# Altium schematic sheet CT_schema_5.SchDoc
size 368 x 243 mm
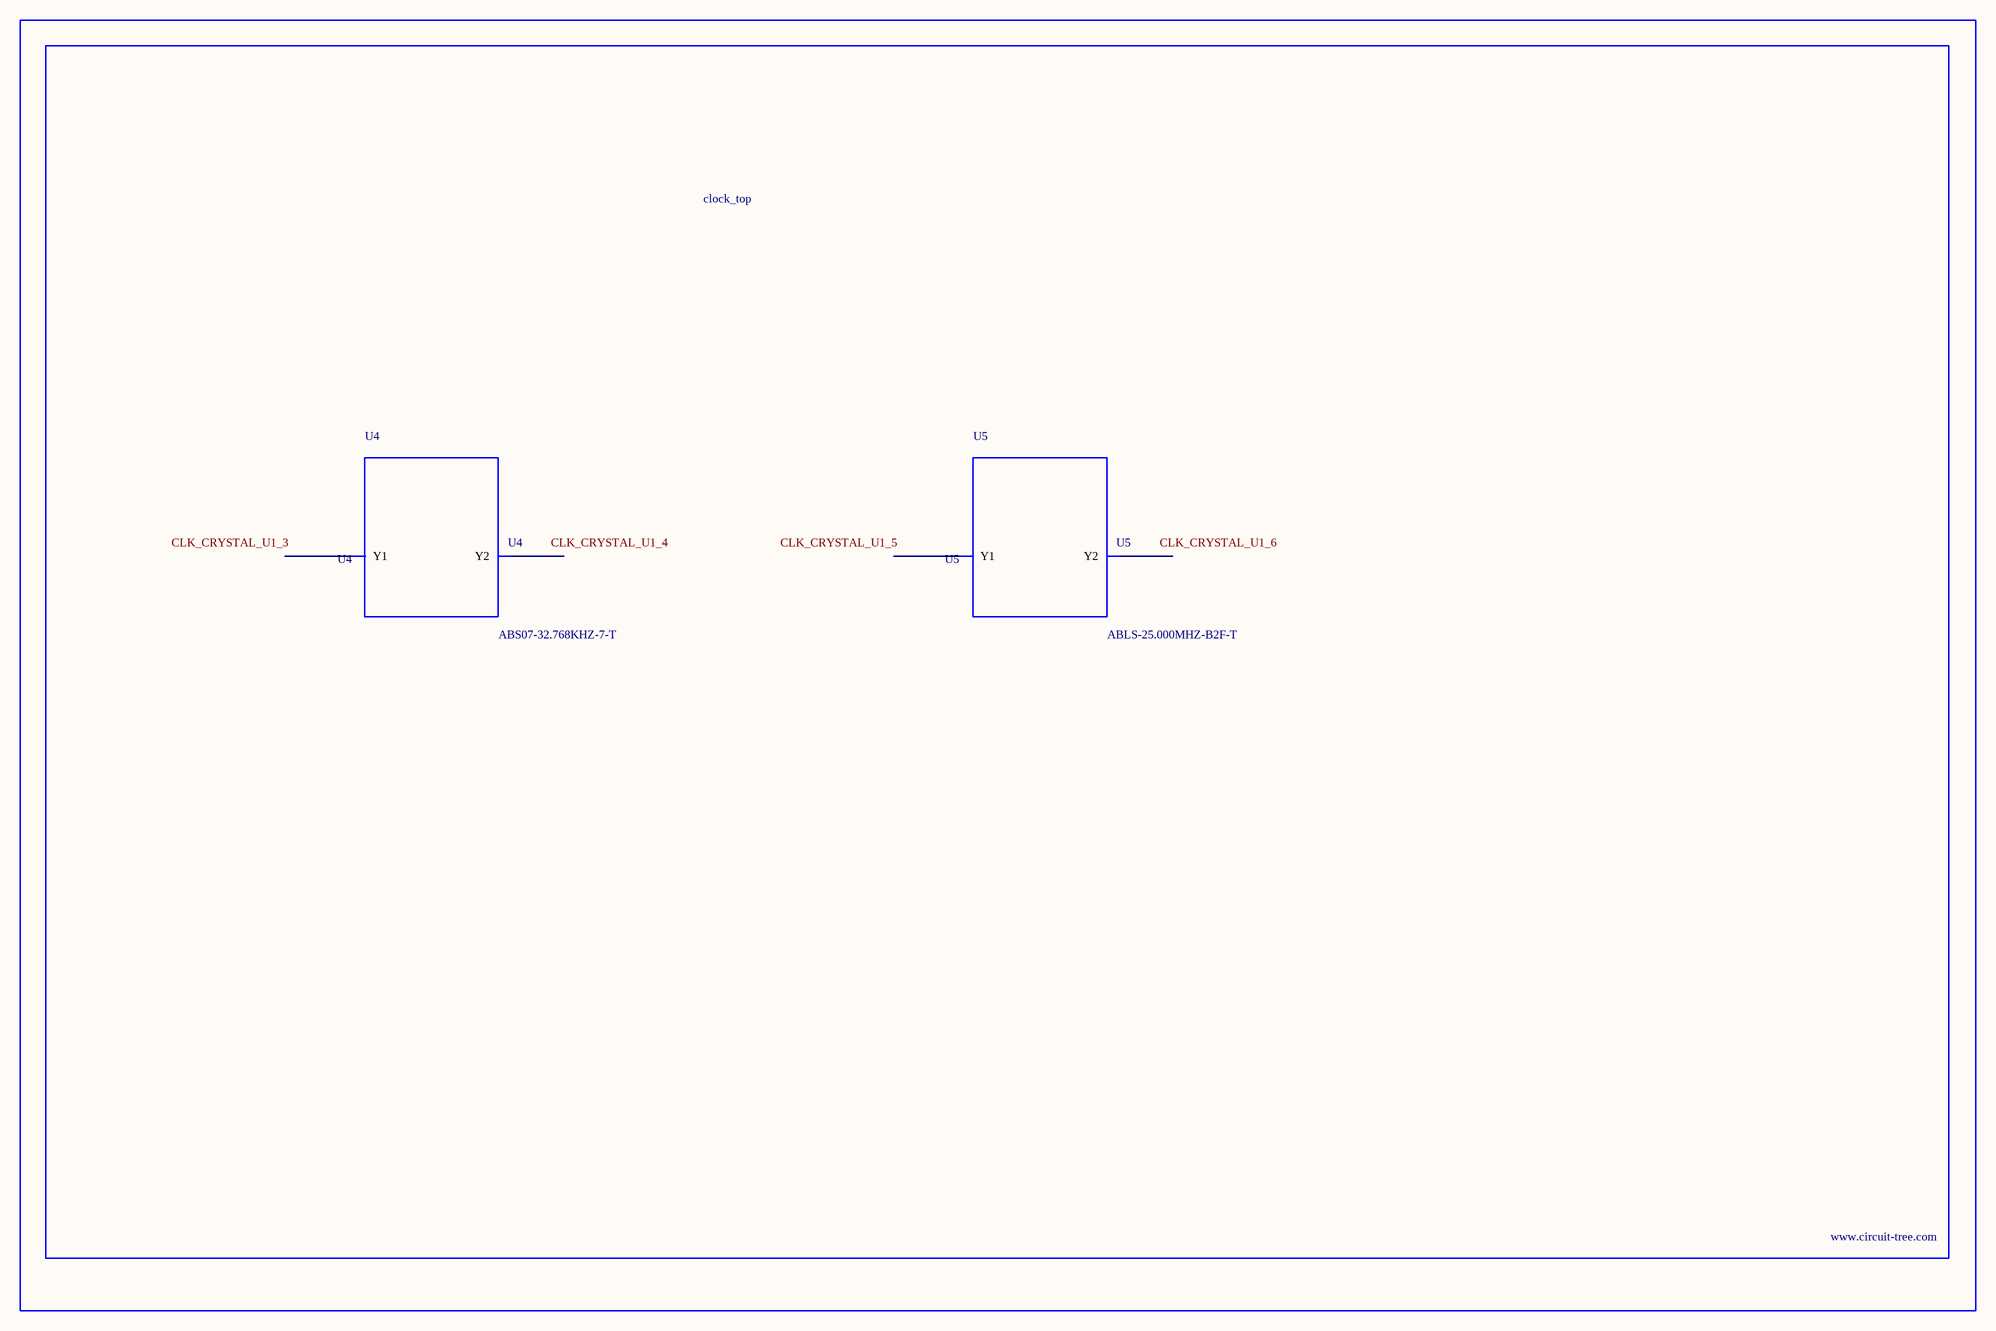
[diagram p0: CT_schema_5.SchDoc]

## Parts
BORDER4  (no value)
U4  ABS07-32.768KHZ-7-T  [ABS07-32.768KHZ-7-T]
U5  ABLS-25.000MHZ-B2F-T  [ABLS-25.000MHZ-B2F-T]

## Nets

Not connected (* = marked no-connect by the designer): U4 1(Y1) 2(Y2); U5 1(Y1) 2(Y2)

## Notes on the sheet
- Labels drawn without touching a wire or pin: CLK_CRYSTAL_U1_3, CLK_CRYSTAL_U1_4, CLK_CRYSTAL_U1_5, CLK_CRYSTAL_U1_6

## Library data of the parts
BORDER4 = BORDER_PAGE4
